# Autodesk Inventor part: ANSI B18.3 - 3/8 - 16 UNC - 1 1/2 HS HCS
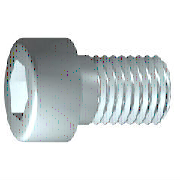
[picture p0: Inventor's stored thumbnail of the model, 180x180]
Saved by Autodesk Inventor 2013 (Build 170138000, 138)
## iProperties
IsCustomPart: 0
Created: 2008-02
Part Number: ANSI B18.3 - 3/8 - 16 UNC - 1 1/2 HS HCS
Material: Steel, Mild
Description: Hexagon Socket Head Cap Screw
Document SubType Name: Modeling
Standard: ANSI B18.3
Designer: tmk
Standard Revision: 2003
Standards Organization: ANSI
Language: en-US
Size Designation: 3/8 - 16 UNC - 1 1/2
Categories: <MemberInstance><Categories><Category DisplayName="Fasteners" InternalName="e4da775c-781d-43d5-af7c-5136215cf5a6" Mnemonic="FSTN"><Category DisplayName="Bolts"
Density: 1 g/cm^3
Author: tmk
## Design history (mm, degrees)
sketch "Sketch1"
  geometry: L1 (-2.261, 0)-(38.1, 0); L2 (38.1, 0)-(38.1, 4.763); L3 (38.1, 4.763)-(3.969, 4.762); L4 (3.969, 4.762)-(0, 4.763); L5 (0, 4.763)-(0, 4.763); L6 (0, 4.763)-(0, 7.137); L7 (0, 7.137)-(-9.525, 7.137); L8 (-9.525, 7.137)-(-9.525, 4.575); L9 (-9.525, 4.575)-(-4.902, 4.575); L10 (-4.902, 4.575)-(-2.261, 0); L11 (-19.05, 0)-(47.625, 0) reference; L12 (0, -1.427)-(0, 8.565) reference; L13 (3.969, 4.762)-(0, 4.762)
  constraints: 22 end point, 6 parallel, 2 collinear, 2 perpendicular, 1 horizontal, 1 point on line
  dimensions: "d1" = 34.13105 distance from line of L3.end L2 (= GEL); "d2" = 3.96885 distance of L4.end L3.end (computed from GAL); "d3" = 9.525 distance between parallel lines of L8 L6 (= KOH); "d4" = 4.6228 distance of L8.end L9.end (= INTI); "d5" = 60 deg angle of L10 L1; "d6" = 9.525 diameter of L3 L1 (= GD); "d7" = 9.525 diameter of L5 L1 (= BDM); "d8" = 9.15077 diameter of L9 L1 (= 1.1547 x SW); "d9" = 14.2748 diameter of L7 L1 (= KOD); "d26" = 38.1 distance between parallel lines of L12 L2 (= NLG)
revolve "Body" sketch "Sketch1" stored, may be unused: angle "d10" = 90 deg
sketch "Sketch2"
  geometry: L1 (0, -9.992)-(0, 9.992) reference; L2 (-9.992, 0)-(9.992, 0) reference; L3 (4.575, 0)-(2.288, -3.962); L4 (2.288, -3.962)-(-2.288, -3.962); L5 (-2.288, -3.962)-(-4.575, 0); L6 (-4.575, 0)-(-2.288, 3.962); L7 (-2.288, 3.962)-(2.288, 3.962); L8 (2.288, 3.962)-(4.575, 0); 2 further points
  constraints: 12 end point, 1 coincident, 1 horizontal alignment, 1 point on line, 12 other
extrude "Slot" join sketch "Sketch2" stored distance "d11" = 10; taper "d12" = 0 deg
workplane "Work Plane1"
fillet "Fillet2" dims "d30" = 0.3048 (= R)
body "Solid1"
fillet "Fillet1" dims "d17" = 0.9652 (= RR)
feature "Thread" dims "d13" = 34.13105 (= GEL), "d14" = 0
chamfer "Chamfer1" distance "d15" = 0.94615 (= -0.5 x SPD + 0.5 x GD); stored, may be unused: second distance "d16" = 0.94615 (= GUL), angle "d27" = 45 deg
other parameters: "GD" = 9.525 (= KOH) [user parameter; used in 2 equation terms], "NLG" = 38.1 [user parameter; used in 1 equation term], "GEL" = 34.13105 [user parameter; used in 2 equation terms], "KOD" = 14.2748 [user parameter; used in 1 equation term], "KOH" = 9.525 [user parameter; used in 3 equation terms], "INTI" = 4.6228 [user parameter; used in 1 equation term], "GAL" = 3.96875 [user parameter; used in 1 equation term], "GUL" = 0.94615 [user parameter; used in 1 equation term], "BDM" = 9.525 (= KOH) [user parameter; used in 1 equation term], "SW" = 7.9248 [user parameter; used in 2 equation terms], "RR" = 0.9652 [user parameter; used in 1 equation term], "SPD" = 7.6327 [user parameter; used in 2 equation terms], "d19" = 0, "d28" = 0, "d29" = 0, "R" = 0.3048 [user parameter; used in 1 equation term], "PHH" = 0.2032 [user parameter], "GD1" = 7.6327 (= SPD) [user parameter], "THREADDIA" = 9.525 [user parameter], "FAWI" = 45 deg [user parameter], "PTC" = 1.5875 (computed from TPU) [user parameter], "KOH1" = 8.5598 [user parameter], "NND" = 9.525 [user parameter], "TOA" = 30 deg [user parameter], "E0" = 9.15314 (= 1.155 x SW) [user parameter]
